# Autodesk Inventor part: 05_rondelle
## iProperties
Shininess: 20.0
Length Units: 11270
Angle Units: 11279
Time Units: 11290
Mass Units: 11283
Length Display Precision: 3
Angle Display Precision: 2
Created: 2000-10
Part Number: 05_rondelle
Material: Par défaut
Document SubType Name: Modélisation
Density: 0.0
Volumn: 0.0
Area: 0.0
PropertySet Name: Model Information
Control State: 0
Master: False
Checked Out: False
Author: Laurent GAUTHERON
